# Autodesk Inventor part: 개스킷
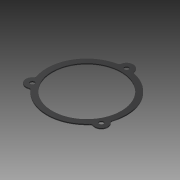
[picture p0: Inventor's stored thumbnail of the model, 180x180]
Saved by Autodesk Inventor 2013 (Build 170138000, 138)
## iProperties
Created: 2018-05
Part Number: 개스킷
Material: 고무, 실리콘
Document SubType Name: Modeling
Designer: mduedu
Density: 1.25 g/cm^3
Mass: 4.51207 g
Surface Area: 58.5509 cm^2
Volume: 3.60966 cm^3
Author: mduedu
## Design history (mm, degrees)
sketch "스케치1"
  geometry: L1 (0, 52)-(0, 0); L2 (0, 0)-(-45.033, -26); L3 (0, 0)-(45.033, -26); C1 r 3 at (-45.033, -26); C2 r 3 at (0, 52); C3 r 3 at (45.033, -26); C4 r 45 at (0, 0); A1 r 3 centre (-40.927, -36.742) between (-38.695, -34.738) and (-41.998, -33.94); A2 r 8.5 centre (-45.033, -26) between (-50.392, -19.402) and (-41.998, -33.94); A3 r 3 centre (-52.283, -17.073) between (-50.392, -19.402) and (-49.431, -16.142); A4 r 52 centre (0, 0) between (-10.736, 50.88) and (-49.431, -16.142); A5 r 3 centre (-11.356, 53.815) between (-10.736, 50.88) and (-8.393, 53.341); A6 r 8.5 centre (0, 52) between (8.393, 53.341) and (-8.393, 53.341); A7 r 3 centre (11.356, 53.815) between (8.393, 53.341) and (10.736, 50.88); A8 r 52 centre (0, 0) between (49.431, -16.142) and (10.736, 50.88); A9 r 3 centre (52.283, -17.073) between (49.431, -16.142) and (50.392, -19.402); A10 r 8.5 centre (45.033, -26) between (41.998, -33.94) and (50.392, -19.402); A11 r 3 centre (40.927, -36.742) between (41.998, -33.94) and (38.695, -34.738); A12 r 52 centre (0, 0) between (-38.695, -34.738) and (38.695, -34.738); 1 further point
  constraints: 24 point on circle, 16 centre point, 12 tangent, 11 equal radius, 6 concentric, 6 end point, 2 coincident, 2 equal length, 2 vertical alignment, 1 vertical
  dimensions: "d1" = 90 diameter of C4; "d3" = 52 radius of A8; "d4" = 3 radius of A7; "d5" = 8.5 radius of A6; "d6" = 120 deg angle of L2 L1; "d7" = 120 deg angle of L3 L1; "d8" = 6 diameter of C2; "d9" = 52 distance of L1.start L1.end
extrude "돌출1" new body sketch "스케치1" distance "d10" = 1.5; taper "d11" = 0 deg
node "솔리드1"
